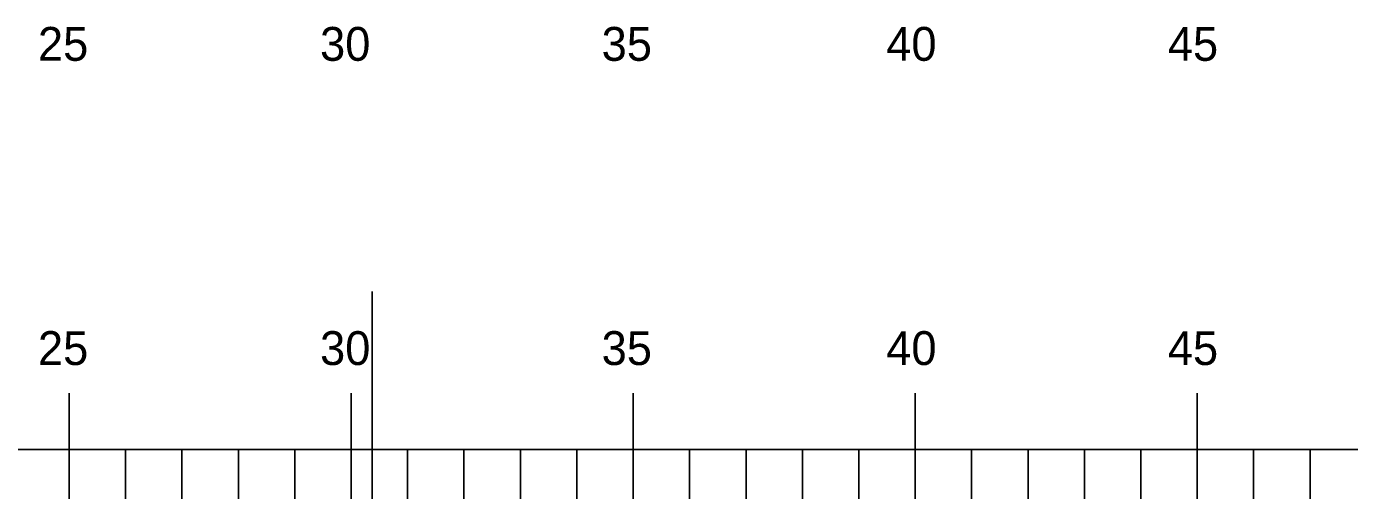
# Model space of a CAD drawing. Extents: x 856235 to 856405, y 366268 to 366378.
# Drawn here: x 856342.02 to 856365.48, y 366315.17 to 366323.39 of the extents above; entities that cross this region are included whole.
import ezdxf

# ---------------------------------------------------------------- set-up
doc = ezdxf.new("R2010")
doc.units = 0
for name, color, linetype in [('E_ROW_Line', 7, 'Continuous'), ('H_V ANNOTATION', 7, 'Continuous'), ('MAJOR', 7, 'Continuous'), ('MINOR', 7, 'Continuous')]:
    doc.layers.add(name, color=color, linetype=linetype)

msp = doc.modelspace()

# ---------------------------------------------------------------- linework, layer by layer
at = {"layer": 'E_ROW_Line'}
msp.add_line((856348.153, 366308.696), (856348.153, 366318.696), dxfattribs=at)
at = {"layer": 'MAJOR'}
for p, q in [((856342.781, 366316.895), (856342.781, 366315.893)), ((856347.781, 366316.895), (856347.781, 366315.893)), ((856352.781, 366316.895), (856352.781, 366315.893)), ((856357.781, 366316.895), (856357.781, 366315.893)), ((856362.781, 366316.895), (856362.781, 366315.893)), ((856247.781, 366315.893), (856387.781, 366315.893)), ((856247.781, 366315.893), (856387.781, 366315.893)), ((856342.781, 366300.893), (856342.781, 366315.893)), ((856347.781, 366300.893), (856347.781, 366315.893)), ((856352.781, 366300.893), (856352.781, 366315.893)), ((856357.781, 366300.893), (856357.781, 366315.893)), ((856362.781, 366300.893), (856362.781, 366315.893))]:
    msp.add_line(p, q, dxfattribs=at)
at = {"layer": 'MINOR'}
for p, q in [((856343.781, 366300.893), (856343.781, 366315.893)), ((856344.781, 366300.893), (856344.781, 366315.893)), ((856345.781, 366300.893), (856345.781, 366315.893)), ((856346.781, 366300.893), (856346.781, 366315.893)), ((856348.781, 366300.893), (856348.781, 366315.893)), ((856349.781, 366300.893), (856349.781, 366315.893)), ((856350.781, 366300.893), (856350.781, 366315.893)), ((856351.781, 366300.893), (856351.781, 366315.893)), ((856353.781, 366300.893), (856353.781, 366315.893)), ((856354.781, 366300.893), (856354.781, 366315.893)), ((856355.781, 366300.893), (856355.781, 366315.893)), ((856356.781, 366300.893), (856356.781, 366315.893)), ((856358.781, 366300.893), (856358.781, 366315.893)), ((856359.781, 366300.893), (856359.781, 366315.893)), ((856360.781, 366300.893), (856360.781, 366315.893)), ((856361.781, 366300.893), (856361.781, 366315.893)), ((856363.781, 366300.893), (856363.781, 366315.893)), ((856364.781, 366300.893), (856364.781, 366315.893))]:
    msp.add_line(p, q, dxfattribs=at)

# ---------------------------------------------------------------- texts
at = {"layer": 'H_V ANNOTATION'}
for s, p in [('25', (856342.227, 366322.785)), ('30', (856347.229, 366322.785)), ('35', (856352.221, 366322.785)), ('40', (856357.267, 366322.785)), ('45', (856362.259, 366322.785)), ('25', (856342.227, 366317.393)), ('30', (856347.229, 366317.393)), ('35', (856352.221, 366317.393)), ('40', (856357.267, 366317.393)), ('45', (856362.259, 366317.393))]:
    msp.add_text(s, height=0.6, dxfattribs=at).set_placement(p)

doc.saveas('drawing.dxf')
